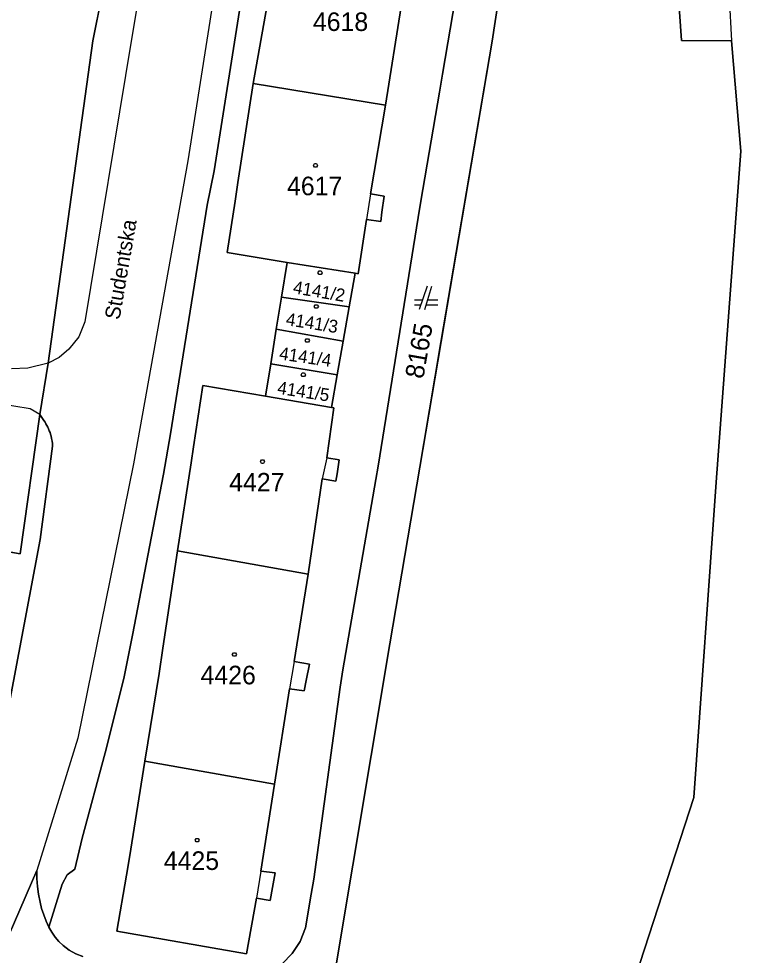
# Model space of a CAD drawing. Extents: x -263587 to -261993, y -1238795 to -1236748.
# Drawn here: x -262804.6 to -262742.4, y -1237578.8 to -1237498.1 of the extents above; entities that cross this region are included whole.
import ezdxf

# ---------------------------------------------------------------- set-up
doc = ezdxf.new("R2010")
doc.units = 0
for name, color, linetype in [('Vrstva 1', 7, 'Continuous'), ('Vrstva 2', 7, 'Continuous'), ('Vrstva 3', 7, 'Continuous')]:
    doc.layers.add(name, color=color, linetype=linetype)

msp = doc.modelspace()

# ---------------------------------------------------------------- linework, layer by layer
at = {"layer": 'Vrstva 1'}
for p, q in [((-262788.52, -1237449.61), (-262798.23, -1237499.99)), ((-262798.23, -1237499.99), (-262788.52, -1237449.61)), ((-262786.6, -1237449.63), (-262794.94, -1237500.04)), ((-262757.02, -1237455.96), (-262763.86, -1237500.03)), ((-262763.86, -1237500.03), (-262757.02, -1237455.96)), ((-262784.59, -1237475.35), (-262790.06, -1237510.34)), ((-262747.55, -1237499.97), (-262749.11, -1237476.18)), ((-262749.11, -1237476.18), (-262747.55, -1237499.97)), ((-262744.47, -1237476), (-262743.25, -1237500.01)), ((-262785.45, -1237496.26), (-262787.79, -1237511.2)), ((-262787.79, -1237511.2), (-262785.45, -1237496.26)), ((-262784.44, -1237503.68), (-262783.01, -1237495.75)), ((-262783.01, -1237495.75), (-262784.44, -1237503.68)), ((-262768.14, -1237502.86), (-262767.01, -1237496.26)), ((-262767.01, -1237496.26), (-262768.14, -1237502.86)), ((-262771.7, -1237497.05), (-262773.03, -1237505.54)), ((-262773.03, -1237505.54), (-262771.7, -1237497.05)), ((-262798.23, -1237499.99), (-262802.08, -1237527.77)), ((-262802.08, -1237527.77), (-262798.23, -1237499.99)), ((-262794.94, -1237500.04), (-262798.93, -1237524.21)), ((-262763.86, -1237500.03), (-262772.66, -1237551.95)), ((-262772.66, -1237551.95), (-262763.86, -1237500.03)), ((-262743.25, -1237500.01), (-262747.55, -1237499.97)), ((-262747.55, -1237499.97), (-262743.25, -1237500.01)), ((-262742.42, -1237509.51), (-262743.25, -1237500.01)), ((-262743.25, -1237500.01), (-262742.42, -1237509.51)), ((-262768.4, -1237504.42), (-262768.14, -1237502.86)), ((-262768.14, -1237502.86), (-262768.4, -1237504.42)), ((-262785.75, -1237512.21), (-262784.44, -1237503.68)), ((-262784.44, -1237503.68), (-262785.75, -1237512.21)), ((-262773.03, -1237505.54), (-262784.44, -1237503.68)), ((-262784.44, -1237503.68), (-262773.03, -1237505.54)), ((-262770, -1237513.81), (-262768.4, -1237504.42)), ((-262768.4, -1237504.42), (-262770, -1237513.81)), ((-262773.03, -1237505.54), (-262774.33, -1237513.17)), ((-262774.33, -1237513.17), (-262773.03, -1237505.54)), ((-262744.57, -1237538.03), (-262742.42, -1237509.51)), ((-262742.42, -1237509.51), (-262744.57, -1237538.03)), ((-262790.06, -1237510.34), (-262794.74, -1237536.43)), ((-262787.79, -1237511.2), (-262788.39, -1237514.16)), ((-262788.39, -1237514.16), (-262787.79, -1237511.2)), ((-262785.99, -1237513.82), (-262785.75, -1237512.21)), ((-262785.75, -1237512.21), (-262785.99, -1237513.82)), ((-262774.33, -1237513.17), (-262774.66, -1237515.38)), ((-262774.33, -1237513.17), (-262773.16, -1237513.38)), ((-262773.16, -1237513.38), (-262774.33, -1237513.17)), ((-262788.39, -1237514.16), (-262791.56, -1237533.86)), ((-262791.56, -1237533.86), (-262788.39, -1237514.16)), ((-262786.67, -1237518.24), (-262785.99, -1237513.82)), ((-262785.99, -1237513.82), (-262786.67, -1237518.24)), ((-262773.16, -1237513.38), (-262773.34, -1237514.76)), ((-262773.34, -1237514.76), (-262773.16, -1237513.38)), ((-262770.23, -1237515.23), (-262770, -1237513.81)), ((-262770, -1237513.81), (-262770.23, -1237515.23)), ((-262773.34, -1237514.76), (-262773.45, -1237515.56)), ((-262773.45, -1237515.56), (-262773.34, -1237514.76)), ((-262774.66, -1237515.38), (-262775.38, -1237520.08)), ((-262775.38, -1237520.08), (-262774.66, -1237515.38)), ((-262773.45, -1237515.56), (-262774.66, -1237515.38)), ((-262774.66, -1237515.38), (-262773.45, -1237515.56)), ((-262773.66, -1237536.64), (-262770.23, -1237515.23)), ((-262770.23, -1237515.23), (-262773.66, -1237536.64)), ((-262803.65, -1237531.7), (-262883.01, -1237518.97)), ((-262781.51, -1237519.1), (-262786.67, -1237518.24)), ((-262786.67, -1237518.24), (-262781.51, -1237519.1)), ((-262781.99, -1237522.09), (-262781.51, -1237519.1)), ((-262781.51, -1237519.1), (-262781.99, -1237522.09)), ((-262775.65, -1237520.02), (-262781.51, -1237519.1)), ((-262781.51, -1237519.1), (-262775.65, -1237520.02)), ((-262775.65, -1237520.02), (-262776.16, -1237522.91)), ((-262776.16, -1237522.91), (-262775.65, -1237520.02)), ((-262775.38, -1237520.08), (-262775.65, -1237520.02)), ((-262775.65, -1237520.02), (-262775.38, -1237520.08)), ((-262769.44, -1237521.13), (-262770.14, -1237523.13)), ((-262769.64, -1237523.13), (-262769.04, -1237521.13)), ((-262782.44, -1237524.83), (-262781.99, -1237522.09)), ((-262781.99, -1237522.09), (-262782.44, -1237524.83)), ((-262781.99, -1237522.09), (-262776.16, -1237522.91)), ((-262776.16, -1237522.91), (-262781.99, -1237522.09)), ((-262776.16, -1237522.91), (-262776.68, -1237525.86)), ((-262776.68, -1237525.86), (-262776.16, -1237522.91)), ((-262769.86, -1237522.33), (-262770.54, -1237522.33)), ((-262770.54, -1237522.73), (-262770, -1237522.73)), ((-262769.52, -1237522.73), (-262768.54, -1237522.73)), ((-262768.54, -1237522.33), (-262769.4, -1237522.33)), ((-262798.93, -1237524.21), (-262799.45, -1237525.49)), ((-262782.92, -1237527.81), (-262782.44, -1237524.83)), ((-262782.44, -1237524.83), (-262782.92, -1237527.81)), ((-262782.44, -1237524.83), (-262776.68, -1237525.86)), ((-262776.68, -1237525.86), (-262782.44, -1237524.83)), ((-262799.45, -1237525.49), (-262800.31, -1237526.57)), ((-262776.68, -1237525.86), (-262777.19, -1237528.77)), ((-262777.19, -1237528.77), (-262776.68, -1237525.86)), ((-262800.31, -1237526.57), (-262801.13, -1237527.27)), ((-262802.08, -1237527.77), (-262803.83, -1237528.2)), ((-262802.08, -1237527.77), (-262802.82, -1237532.2)), ((-262802.82, -1237532.2), (-262802.08, -1237527.77)), ((-262801.13, -1237527.27), (-262802.08, -1237527.77)), ((-262783.38, -1237530.6), (-262782.92, -1237527.81)), ((-262782.92, -1237527.81), (-262783.38, -1237530.6)), ((-262777.19, -1237528.77), (-262782.92, -1237527.81)), ((-262782.92, -1237527.81), (-262777.19, -1237528.77)), ((-262803.83, -1237528.2), (-262805.25, -1237528.24)), ((-262777.19, -1237528.77), (-262777.68, -1237531.57)), ((-262777.68, -1237531.57), (-262777.19, -1237528.77)), ((-262789.57, -1237534.98), (-262788.76, -1237529.68)), ((-262788.76, -1237529.68), (-262789.57, -1237534.98)), ((-262788.76, -1237529.68), (-262783.38, -1237530.6)), ((-262783.38, -1237530.6), (-262788.76, -1237529.68)), ((-262777.68, -1237531.57), (-262783.38, -1237530.6)), ((-262783.38, -1237530.6), (-262777.68, -1237531.57)), ((-262802.82, -1237532.2), (-262803.65, -1237531.7)), ((-262777.5, -1237531.6), (-262778.08, -1237535.93)), ((-262778.08, -1237535.93), (-262777.5, -1237531.6)), ((-262777.68, -1237531.57), (-262777.5, -1237531.6)), ((-262777.5, -1237531.6), (-262777.68, -1237531.57)), ((-262804.49, -1237544.2), (-262802.82, -1237532.2)), ((-262802.82, -1237532.2), (-262804.49, -1237544.2)), ((-262802.82, -1237532.2), (-262802.7, -1237532.36)), ((-262802.7, -1237532.36), (-262802.82, -1237532.2)), ((-262802.7, -1237532.36), (-262802.58, -1237532.52)), ((-262802.58, -1237532.52), (-262802.7, -1237532.36)), ((-262802.58, -1237532.52), (-262802.47, -1237532.69)), ((-262802.47, -1237532.69), (-262802.58, -1237532.52)), ((-262802.47, -1237532.69), (-262802.36, -1237532.86)), ((-262802.36, -1237532.86), (-262802.47, -1237532.69)), ((-262802.36, -1237532.86), (-262802.28, -1237533)), ((-262802.28, -1237533), (-262802.36, -1237532.86)), ((-262802.28, -1237533), (-262802.2, -1237533.14)), ((-262802.2, -1237533.14), (-262802.28, -1237533)), ((-262802.2, -1237533.14), (-262802.13, -1237533.29)), ((-262802.13, -1237533.29), (-262802.2, -1237533.14)), ((-262802.13, -1237533.29), (-262802.06, -1237533.43)), ((-262802.06, -1237533.43), (-262802.13, -1237533.29)), ((-262802.06, -1237533.43), (-262801.99, -1237533.58)), ((-262801.99, -1237533.58), (-262802.06, -1237533.43)), ((-262801.99, -1237533.58), (-262801.93, -1237533.73)), ((-262801.93, -1237533.73), (-262801.99, -1237533.58)), ((-262801.93, -1237533.73), (-262801.88, -1237533.89)), ((-262801.88, -1237533.89), (-262801.93, -1237533.73)), ((-262801.88, -1237533.89), (-262801.84, -1237534.04)), ((-262801.84, -1237534.04), (-262801.88, -1237533.89)), ((-262801.84, -1237534.04), (-262801.79, -1237534.25)), ((-262801.79, -1237534.25), (-262801.84, -1237534.04)), ((-262801.79, -1237534.25), (-262801.75, -1237534.47)), ((-262801.75, -1237534.47), (-262801.79, -1237534.25)), ((-262791.56, -1237533.86), (-262792.17, -1237537.34)), ((-262792.17, -1237537.34), (-262791.56, -1237533.86)), ((-262801.72, -1237534.91), (-262802.78, -1237542.95)), ((-262802.78, -1237542.95), (-262801.72, -1237534.91)), ((-262801.75, -1237534.47), (-262801.73, -1237534.69)), ((-262801.73, -1237534.69), (-262801.75, -1237534.47)), ((-262801.73, -1237534.69), (-262801.72, -1237534.91)), ((-262801.72, -1237534.91), (-262801.73, -1237534.69)), ((-262789.78, -1237536.36), (-262789.57, -1237534.98)), ((-262789.57, -1237534.98), (-262789.78, -1237536.36)), ((-262778.08, -1237535.93), (-262778.49, -1237537.72)), ((-262778.08, -1237535.93), (-262777.02, -1237536.09)), ((-262777.02, -1237536.09), (-262778.08, -1237535.93)), ((-262794.74, -1237536.43), (-262799.52, -1237560.08)), ((-262790.94, -1237543.94), (-262789.78, -1237536.36)), ((-262789.78, -1237536.36), (-262790.94, -1237543.94)), ((-262777.02, -1237536.09), (-262777.21, -1237537.3)), ((-262777.21, -1237537.3), (-262777.02, -1237536.09)), ((-262773.86, -1237537.79), (-262773.66, -1237536.64)), ((-262773.66, -1237536.64), (-262773.86, -1237537.79)), ((-262792.17, -1237537.34), (-262794.83, -1237551.2)), ((-262794.83, -1237551.2), (-262792.17, -1237537.34)), ((-262777.21, -1237537.3), (-262777.3, -1237537.92)), ((-262777.3, -1237537.92), (-262777.21, -1237537.3)), ((-262778.49, -1237537.72), (-262779.71, -1237545.93)), ((-262779.71, -1237545.93), (-262778.49, -1237537.72)), ((-262777.3, -1237537.92), (-262778.49, -1237537.72)), ((-262778.49, -1237537.72), (-262777.3, -1237537.92)), ((-262776.72, -1237554.18), (-262773.86, -1237537.79)), ((-262773.86, -1237537.79), (-262776.72, -1237554.18)), ((-262746.49, -1237565.17), (-262744.57, -1237538.03)), ((-262744.57, -1237538.03), (-262746.49, -1237565.17)), ((-262802.78, -1237542.95), (-262806, -1237560.05)), ((-262806, -1237560.05), (-262802.78, -1237542.95)), ((-262807.44, -1237543.66), (-262804.49, -1237544.2)), ((-262804.49, -1237544.2), (-262807.44, -1237543.66)), ((-262792.21, -1237552.33), (-262790.94, -1237543.94)), ((-262790.94, -1237543.94), (-262792.21, -1237552.33)), ((-262779.71, -1237545.93), (-262790.94, -1237543.94)), ((-262790.94, -1237543.94), (-262779.71, -1237545.93)), ((-262779.71, -1237545.93), (-262780.89, -1237553.47)), ((-262780.89, -1237553.47), (-262779.71, -1237545.93)), ((-262794.83, -1237551.2), (-262795.58, -1237554.94)), ((-262795.58, -1237554.94), (-262794.83, -1237551.2)), ((-262772.66, -1237551.95), (-262777.67, -1237581.91)), ((-262777.67, -1237581.91), (-262772.66, -1237551.95)), ((-262792.53, -1237554.51), (-262792.21, -1237552.33)), ((-262792.21, -1237552.33), (-262792.53, -1237554.51)), ((-262780.89, -1237553.47), (-262781.3, -1237555.81)), ((-262780.89, -1237553.47), (-262779.59, -1237553.7)), ((-262779.59, -1237553.7), (-262780.89, -1237553.47)), ((-262779.59, -1237553.7), (-262779.87, -1237555.09)), ((-262779.87, -1237555.09), (-262779.59, -1237553.7)), ((-262776.93, -1237555.67), (-262776.72, -1237554.18)), ((-262776.72, -1237554.18), (-262776.93, -1237555.67)), ((-262795.58, -1237554.94), (-262797.17, -1237561.34)), ((-262797.17, -1237561.34), (-262795.58, -1237554.94)), ((-262793.77, -1237562.05), (-262792.53, -1237554.51)), ((-262792.53, -1237554.51), (-262793.77, -1237562.05)), ((-262779.87, -1237555.09), (-262780.05, -1237556)), ((-262780.05, -1237556), (-262779.87, -1237555.09)), ((-262781.3, -1237555.81), (-262782.59, -1237564.03)), ((-262782.59, -1237564.03), (-262781.3, -1237555.81)), ((-262780.05, -1237556), (-262781.3, -1237555.81)), ((-262781.3, -1237555.81), (-262780.05, -1237556)), ((-262779.22, -1237572.21), (-262776.93, -1237555.67)), ((-262776.93, -1237555.67), (-262779.22, -1237572.21)), ((-262799.52, -1237560.08), (-262803.07, -1237571.46)), ((-262797.17, -1237561.34), (-262799.15, -1237568.68)), ((-262799.15, -1237568.68), (-262797.17, -1237561.34)), ((-262795.09, -1237570.36), (-262793.77, -1237562.05)), ((-262793.77, -1237562.05), (-262795.09, -1237570.36)), ((-262782.59, -1237564.03), (-262793.77, -1237562.05)), ((-262793.77, -1237562.05), (-262782.59, -1237564.03)), ((-262782.59, -1237564.03), (-262783.77, -1237571.53)), ((-262783.77, -1237571.53), (-262782.59, -1237564.03)), ((-262760.18, -1237607.41), (-262746.49, -1237565.17)), ((-262746.49, -1237565.17), (-262760.18, -1237607.41)), ((-262799.15, -1237568.68), (-262799.8, -1237571.36)), ((-262799.8, -1237571.36), (-262799.15, -1237568.68)), ((-262795.35, -1237571.87), (-262795.09, -1237570.36)), ((-262795.09, -1237570.36), (-262795.35, -1237571.87)), ((-262799.8, -1237571.36), (-262800.46, -1237571.85)), ((-262800.46, -1237571.85), (-262799.8, -1237571.36)), ((-262809.01, -1237585.16), (-262803.07, -1237571.46)), ((-262803.07, -1237571.46), (-262809.01, -1237585.16)), ((-262803.07, -1237571.46), (-262803.07, -1237572.15)), ((-262803.07, -1237572.15), (-262803.07, -1237571.46)), ((-262803.07, -1237572.15), (-262803.02, -1237572.84)), ((-262803.02, -1237572.84), (-262803.07, -1237572.15)), ((-262800.46, -1237571.85), (-262800.87, -1237572.65)), ((-262800.87, -1237572.65), (-262800.46, -1237571.85)), ((-262796.17, -1237576.69), (-262795.35, -1237571.87)), ((-262795.35, -1237571.87), (-262796.17, -1237576.69)), ((-262783.77, -1237571.53), (-262784.16, -1237573.84)), ((-262783.77, -1237571.53), (-262782.55, -1237571.67)), ((-262782.55, -1237571.67), (-262783.77, -1237571.53)), ((-262782.55, -1237571.67), (-262782.78, -1237572.94)), ((-262782.78, -1237572.94), (-262782.55, -1237571.67)), ((-262779.44, -1237573.51), (-262779.22, -1237572.21)), ((-262779.22, -1237572.21), (-262779.44, -1237573.51)), ((-262803.02, -1237572.84), (-262802.93, -1237573.52)), ((-262802.93, -1237573.52), (-262803.02, -1237572.84)), ((-262800.87, -1237572.65), (-262802.02, -1237576.35)), ((-262802.02, -1237576.35), (-262800.87, -1237572.65)), ((-262782.78, -1237572.94), (-262782.97, -1237574.06)), ((-262782.97, -1237574.06), (-262782.78, -1237572.94)), ((-262802.93, -1237573.52), (-262802.79, -1237574.19)), ((-262802.79, -1237574.19), (-262802.93, -1237573.52)), ((-262784.16, -1237573.84), (-262785.02, -1237578.66)), ((-262785.02, -1237578.66), (-262784.16, -1237573.84)), ((-262782.97, -1237574.06), (-262784.16, -1237573.84)), ((-262784.16, -1237573.84), (-262782.97, -1237574.06)), ((-262779.94, -1237576.41), (-262779.44, -1237573.51)), ((-262779.44, -1237573.51), (-262779.94, -1237576.41)), ((-262802.79, -1237574.19), (-262802.65, -1237574.75)), ((-262802.65, -1237574.75), (-262802.79, -1237574.19)), ((-262802.65, -1237574.75), (-262802.47, -1237575.29)), ((-262802.47, -1237575.29), (-262802.65, -1237574.75)), ((-262802.47, -1237575.29), (-262802.26, -1237575.83)), ((-262802.26, -1237575.83), (-262802.47, -1237575.29)), ((-262802.26, -1237575.83), (-262802.02, -1237576.35)), ((-262802.02, -1237576.35), (-262802.26, -1237575.83)), ((-262802.02, -1237576.35), (-262801.77, -1237576.79)), ((-262801.77, -1237576.79), (-262802.02, -1237576.35)), ((-262801.77, -1237576.79), (-262801.49, -1237577.21)), ((-262801.49, -1237577.21), (-262801.77, -1237576.79)), ((-262785.02, -1237578.66), (-262796.17, -1237576.69)), ((-262796.17, -1237576.69), (-262785.02, -1237578.66)), ((-262780.39, -1237577.58), (-262779.94, -1237576.41)), ((-262779.94, -1237576.41), (-262780.39, -1237577.58)), ((-262801.49, -1237577.21), (-262801.16, -1237577.59)), ((-262801.16, -1237577.59), (-262801.49, -1237577.21)), ((-262801.16, -1237577.59), (-262800.79, -1237577.94)), ((-262800.79, -1237577.94), (-262801.16, -1237577.59)), ((-262781.07, -1237578.63), (-262780.39, -1237577.58)), ((-262780.39, -1237577.58), (-262781.07, -1237578.63)), ((-262800.79, -1237577.94), (-262800.27, -1237578.32)), ((-262800.27, -1237578.32), (-262800.79, -1237577.94)), ((-262800.27, -1237578.32), (-262799.7, -1237578.64)), ((-262799.7, -1237578.64), (-262800.27, -1237578.32)), ((-262799.7, -1237578.64), (-262799.1, -1237578.88)), ((-262799.1, -1237578.88), (-262799.7, -1237578.64)), ((-262781.95, -1237579.51), (-262781.07, -1237578.63)), ((-262781.07, -1237578.63), (-262781.95, -1237579.51))]:
    msp.add_line(p, q, dxfattribs=at)
for points in [[(-262778.97, -1237510.58), (-262778.88, -1237510.73), (-262778.97, -1237510.88), (-262779.15, -1237510.88), (-262779.24, -1237510.73), (-262779.15, -1237510.58)], [(-262778.58, -1237519.82), (-262778.49, -1237519.97), (-262778.58, -1237520.12), (-262778.76, -1237520.12), (-262778.85, -1237519.97), (-262778.76, -1237519.82)], [(-262778.91, -1237522.74), (-262778.82, -1237522.89), (-262778.91, -1237523.04), (-262779.09, -1237523.04), (-262779.18, -1237522.89), (-262779.09, -1237522.74)], [(-262779.68, -1237525.66), (-262779.59, -1237525.81), (-262779.68, -1237525.96), (-262779.86, -1237525.96), (-262779.95, -1237525.81), (-262779.86, -1237525.66)], [(-262780.02, -1237528.61), (-262779.93, -1237528.76), (-262780.02, -1237528.91), (-262780.2, -1237528.91), (-262780.29, -1237528.76), (-262780.2, -1237528.61)], [(-262783.54, -1237536.1), (-262783.45, -1237536.25), (-262783.54, -1237536.4), (-262783.72, -1237536.4), (-262783.81, -1237536.25), (-262783.72, -1237536.1)], [(-262785.96, -1237552.71), (-262785.87, -1237552.86), (-262785.96, -1237553.01), (-262786.14, -1237553.01), (-262786.23, -1237552.86), (-262786.14, -1237552.71)], [(-262789.17, -1237568.7), (-262789.08, -1237568.85), (-262789.17, -1237569), (-262789.35, -1237569), (-262789.44, -1237568.85), (-262789.35, -1237568.7)]]:
    msp.add_lwpolyline(points, close=True, dxfattribs=at)
at = {"layer": 'Vrstva 2'}
msp.add_lwpolyline([(-262784.75, -1237625.31), (-262780.055, -1237596.24), (-262775.165, -1237566.93), (-262768.26, -1237525.99), (-262763.86, -1237500.03), (-262763.86, -1237500.03), (-262757.02, -1237455.96), (-262754.395, -1237429.23), (-262751.77, -1237402.5), (-262750.5, -1237391.48), (-262750.424, -1237380.733), (-262750.315, -1237371.914), (-262750.742, -1237358.967), (-262751.363, -1237345.612), (-262751.817, -1237337.772)], dxfattribs=at)
at = {"layer": 'Vrstva 3'}
msp.add_lwpolyline([(-262781.6, -1237646.81), (-262760.18, -1237607.41), (-262746.49, -1237565.17), (-262744.57, -1237538.03), (-262742.42, -1237509.51), (-262743.25, -1237500.01), (-262747.55, -1237499.97), (-262749.11, -1237476.18), (-262748.79, -1237440.91), (-262747.23, -1237375.51), (-262746.13, -1237308.63), (-262749.07, -1237311.22), (-262749.15, -1237308.17), (-262746.16, -1237306.31), (-262747.51, -1237293.89), (-262747.66, -1237292.16), (-262745.96, -1237291.09), (-262746.395, -1237269.455), (-262745.66, -1237267.05), (-262744.55, -1237267.05), (-262743.43, -1237239.23), (-262748.29, -1237225.02), (-262744.25, -1237230.5), (-262727.51, -1237252.7)], dxfattribs=at)

# ---------------------------------------------------------------- texts
at = {"layer": 'Vrstva 1'}
for s, p in [('4618', (-262779.288, -1237499.15)), ('4617', (-262781.518, -1237513.3)), ('4427', (-262786.498, -1237538.82)), ('4426', (-262788.962, -1237555.43)), ('4425', (-262792.128, -1237571.42))]:
    msp.add_text(s, height=1.6, dxfattribs=at).set_placement(p)
for s, height, rotation, p in [('Studentska', 1.3, 80.15679, (-262795.949, -1237524.081)), ('4141/2', 1.1, 350.36369, (-262781.057, -1237521.736)), ('4141/3', 1.1, 351.10854, (-262781.668, -1237524.486)), ('8165', 1.6, 79.98491, (-262769.787, -1237529.173)), ('4141/4', 1.1, 351.73879, (-262782.239, -1237527.442)), ('4141/5', 1.1, 351.28042, (-262782.405, -1237530.393))]:
    msp.add_text(s, height=height, rotation=rotation, dxfattribs=at).set_placement(p)

doc.saveas('drawing.dxf')
